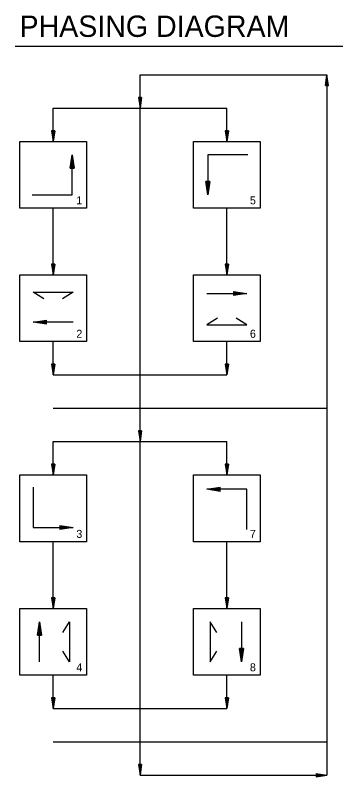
# Model space of a CAD drawing. Extents: x 1 to 35.4, y 0.4 to 10.6.
# Drawn here: x 1.154 to 3.198, y 5.838 to 10.595 of the extents above; entities that cross this region are included whole.
import ezdxf

# ---------------------------------------------------------------- set-up
doc = ezdxf.new("R2010")
doc.units = 0
for name, color, linetype in [('R_Draft', 7, 'Continuous'), ('T_Drafting', 7, 'Continuous'), ('T_Notes', 7, 'Continuous')]:
    doc.layers.add(name, color=color, linetype=linetype)

msp = doc.modelspace()

# ---------------------------------------------------------------- linework, layer by layer
at = {"layer": 'R_Draft'}
for p, q in [((3.0897, 10.1566), (3.0997, 10.2232)), ((3.0913, 10.1566), (3.0997, 10.2121)), ((3.093, 10.1566), (3.0997, 10.2006)), ((3.0947, 10.1566), (3.0997, 10.1895)), ((3.1097, 10.1566), (3.0997, 10.2232)), ((3.108, 10.1566), (3.0997, 10.2121)), ((3.1063, 10.1566), (3.0997, 10.2006)), ((3.1046, 10.1566), (3.0997, 10.1895)), ((3.0897, 10.1566), (3.1097, 10.1566)), ((3.0964, 10.1566), (3.0997, 10.1782)), ((3.0981, 10.1566), (3.0997, 10.1671)), ((3.1029, 10.1566), (3.0997, 10.1782)), ((3.1012, 10.1566), (3.0997, 10.1671)), ((1.923, 10.0816), (1.933, 10.0149)), ((1.943, 10.0816), (1.923, 10.0816)), ((1.9247, 10.0816), (1.933, 10.026)), ((1.9264, 10.0816), (1.933, 10.0375)), ((1.928, 10.0816), (1.933, 10.0486)), ((1.9297, 10.0816), (1.933, 10.0599)), ((1.9314, 10.0816), (1.933, 10.071)), ((1.943, 10.0816), (1.933, 10.0149)), ((1.9362, 10.0816), (1.933, 10.0599)), ((1.9396, 10.0816), (1.933, 10.0375)), ((1.9413, 10.0816), (1.933, 10.026)), ((1.938, 10.0816), (1.933, 10.0486)), ((1.9346, 10.0816), (1.933, 10.071)), ((1.3813, 9.8732), (1.3913, 9.8066)), ((1.4013, 9.8732), (1.3813, 9.8732)), ((1.383, 9.8732), (1.3913, 9.8177)), ((1.3847, 9.8732), (1.3913, 9.8292)), ((1.3864, 9.8732), (1.3913, 9.8403)), ((1.3881, 9.8732), (1.3913, 9.8516)), ((1.3898, 9.8732), (1.3913, 9.8627)), ((1.4013, 9.8732), (1.3913, 9.8066)), ((1.3946, 9.8732), (1.3913, 9.8516)), ((1.398, 9.8732), (1.3913, 9.8292)), ((1.3997, 9.8732), (1.3913, 9.8177)), ((1.3963, 9.8732), (1.3913, 9.8403)), ((1.3929, 9.8732), (1.3913, 9.8627)), ((2.4647, 9.8732), (2.4747, 9.8066)), ((2.4847, 9.8732), (2.4647, 9.8732)), ((2.4663, 9.8732), (2.4747, 9.8177)), ((2.468, 9.8732), (2.4747, 9.8292)), ((2.4697, 9.8732), (2.4747, 9.8403)), ((2.4714, 9.8732), (2.4747, 9.8516)), ((2.4731, 9.8732), (2.4747, 9.8627)), ((2.4847, 9.8732), (2.4747, 9.8066)), ((2.4779, 9.8732), (2.4747, 9.8516)), ((2.4813, 9.8732), (2.4747, 9.8292)), ((2.483, 9.8732), (2.4747, 9.8177)), ((2.4796, 9.8732), (2.4747, 9.8403)), ((2.4762, 9.8732), (2.4747, 9.8627)), ((1.3813, 9.0399), (1.3913, 8.9732)), ((1.4013, 9.0399), (1.3813, 9.0399)), ((1.383, 9.0399), (1.3913, 8.9844)), ((1.3847, 9.0399), (1.3913, 8.9958)), ((1.3864, 9.0399), (1.3913, 9.0069)), ((1.3881, 9.0399), (1.3913, 9.0182)), ((1.3898, 9.0399), (1.3913, 9.0294)), ((1.4013, 9.0399), (1.3913, 8.9732)), ((1.3946, 9.0399), (1.3913, 9.0182)), ((1.398, 9.0399), (1.3913, 8.9958)), ((1.3997, 9.0399), (1.3913, 8.9844)), ((1.3963, 9.0399), (1.3913, 9.0069)), ((1.3929, 9.0399), (1.3913, 9.0294)), ((2.4647, 9.0399), (2.4747, 8.9732)), ((2.4847, 9.0399), (2.4647, 9.0399)), ((2.4663, 9.0399), (2.4747, 8.9844)), ((2.468, 9.0399), (2.4747, 8.9958)), ((2.4697, 9.0399), (2.4747, 9.0069)), ((2.4714, 9.0399), (2.4747, 9.0182)), ((2.4731, 9.0399), (2.4747, 9.0294)), ((2.4847, 9.0399), (2.4747, 8.9732)), ((2.4779, 9.0399), (2.4747, 9.0182)), ((2.4813, 9.0399), (2.4747, 8.9958)), ((2.483, 9.0399), (2.4747, 8.9844)), ((2.4796, 9.0399), (2.4747, 9.0069)), ((2.4762, 9.0399), (2.4747, 9.0294)), ((1.3813, 8.4149), (1.3913, 8.3482)), ((1.4013, 8.4149), (1.3813, 8.4149)), ((1.383, 8.4149), (1.3913, 8.3594)), ((1.3847, 8.4149), (1.3913, 8.3708)), ((1.3864, 8.4149), (1.3913, 8.3819)), ((1.3881, 8.4149), (1.3913, 8.3932)), ((1.3898, 8.4149), (1.3913, 8.4044)), ((1.4013, 8.4149), (1.3913, 8.3482)), ((1.3946, 8.4149), (1.3913, 8.3932)), ((1.398, 8.4149), (1.3913, 8.3708)), ((1.3997, 8.4149), (1.3913, 8.3594)), ((1.3963, 8.4149), (1.3913, 8.3819)), ((1.3929, 8.4149), (1.3913, 8.4044)), ((2.4647, 8.4149), (2.4747, 8.3482)), ((2.4847, 8.4149), (2.4647, 8.4149)), ((2.4663, 8.4149), (2.4747, 8.3594)), ((2.468, 8.4149), (2.4747, 8.3708)), ((2.4697, 8.4149), (2.4747, 8.3819)), ((2.4714, 8.4149), (2.4747, 8.3932)), ((2.4731, 8.4149), (2.4747, 8.4044)), ((2.4847, 8.4149), (2.4747, 8.3482)), ((2.4779, 8.4149), (2.4747, 8.3932)), ((2.4813, 8.4149), (2.4747, 8.3708)), ((2.483, 8.4149), (2.4747, 8.3594)), ((2.4796, 8.4149), (2.4747, 8.3819)), ((2.4762, 8.4149), (2.4747, 8.4044)), ((1.923, 7.9982), (1.933, 7.9316)), ((1.943, 7.9982), (1.923, 7.9982)), ((1.9247, 7.9982), (1.933, 7.9427)), ((1.9264, 7.9982), (1.933, 7.9542)), ((1.928, 7.9982), (1.933, 7.9653)), ((1.9297, 7.9982), (1.933, 7.9766)), ((1.9314, 7.9982), (1.933, 7.9877)), ((1.943, 7.9982), (1.933, 7.9316)), ((1.9362, 7.9982), (1.933, 7.9766)), ((1.9396, 7.9982), (1.933, 7.9542)), ((1.9413, 7.9982), (1.933, 7.9427)), ((1.938, 7.9982), (1.933, 7.9653)), ((1.9346, 7.9982), (1.933, 7.9877)), ((1.3813, 7.7899), (1.3913, 7.7232)), ((1.4013, 7.7899), (1.3813, 7.7899)), ((1.383, 7.7899), (1.3913, 7.7344)), ((1.3847, 7.7899), (1.3913, 7.7458)), ((1.3864, 7.7899), (1.3913, 7.7569)), ((1.3881, 7.7899), (1.3913, 7.7682)), ((1.3898, 7.7899), (1.3913, 7.7794)), ((1.4013, 7.7899), (1.3913, 7.7232)), ((1.3946, 7.7899), (1.3913, 7.7682)), ((1.398, 7.7899), (1.3913, 7.7458)), ((1.3997, 7.7899), (1.3913, 7.7344)), ((1.3963, 7.7899), (1.3913, 7.7569)), ((1.3929, 7.7899), (1.3913, 7.7794)), ((2.4647, 7.7899), (2.4747, 7.7232)), ((2.4847, 7.7899), (2.4647, 7.7899)), ((2.4663, 7.7899), (2.4747, 7.7344)), ((2.468, 7.7899), (2.4747, 7.7458)), ((2.4697, 7.7899), (2.4747, 7.7569)), ((2.4714, 7.7899), (2.4747, 7.7682)), ((2.4731, 7.7899), (2.4747, 7.7794)), ((2.4847, 7.7899), (2.4747, 7.7232)), ((2.4779, 7.7899), (2.4747, 7.7682)), ((2.4813, 7.7899), (2.4747, 7.7458)), ((2.483, 7.7899), (2.4747, 7.7344)), ((2.4796, 7.7899), (2.4747, 7.7569)), ((2.4762, 7.7899), (2.4747, 7.7794)), ((1.3813, 6.9566), (1.3913, 6.8899)), ((1.4013, 6.9566), (1.3813, 6.9566)), ((1.383, 6.9566), (1.3913, 6.901)), ((1.3847, 6.9566), (1.3913, 6.9125)), ((1.3864, 6.9566), (1.3913, 6.9236)), ((1.3881, 6.9566), (1.3913, 6.9349)), ((1.3898, 6.9566), (1.3913, 6.946)), ((1.4013, 6.9566), (1.3913, 6.8899)), ((1.3946, 6.9566), (1.3913, 6.9349)), ((1.398, 6.9566), (1.3913, 6.9125)), ((1.3997, 6.9566), (1.3913, 6.901)), ((1.3963, 6.9566), (1.3913, 6.9236)), ((1.3929, 6.9566), (1.3913, 6.946)), ((2.4647, 6.9566), (2.4747, 6.8899)), ((2.4847, 6.9566), (2.4647, 6.9566)), ((2.4663, 6.9566), (2.4747, 6.901)), ((2.468, 6.9566), (2.4747, 6.9125)), ((2.4697, 6.9566), (2.4747, 6.9236)), ((2.4714, 6.9566), (2.4747, 6.9349)), ((2.4731, 6.9566), (2.4747, 6.946)), ((2.4847, 6.9566), (2.4747, 6.8899)), ((2.4779, 6.9566), (2.4747, 6.9349)), ((2.4813, 6.9566), (2.4747, 6.9125)), ((2.483, 6.9566), (2.4747, 6.901)), ((2.4796, 6.9566), (2.4747, 6.9236)), ((2.4762, 6.9566), (2.4747, 6.946)), ((1.3813, 6.3316), (1.3913, 6.2649)), ((1.4013, 6.3316), (1.3813, 6.3316)), ((1.383, 6.3316), (1.3913, 6.276)), ((1.3847, 6.3316), (1.3913, 6.2875)), ((1.3864, 6.3316), (1.3913, 6.2986)), ((1.3881, 6.3316), (1.3913, 6.3099)), ((1.3898, 6.3316), (1.3913, 6.321)), ((1.4013, 6.3316), (1.3913, 6.2649)), ((1.3946, 6.3316), (1.3913, 6.3099)), ((1.398, 6.3316), (1.3913, 6.2875)), ((1.3997, 6.3316), (1.3913, 6.276)), ((1.3963, 6.3316), (1.3913, 6.2986)), ((1.3929, 6.3316), (1.3913, 6.321)), ((2.4647, 6.3316), (2.4747, 6.2649)), ((2.4847, 6.3316), (2.4647, 6.3316)), ((2.4663, 6.3316), (2.4747, 6.276)), ((2.468, 6.3316), (2.4747, 6.2875)), ((2.4697, 6.3316), (2.4747, 6.2986)), ((2.4714, 6.3316), (2.4747, 6.3099)), ((2.4731, 6.3316), (2.4747, 6.321)), ((2.4847, 6.3316), (2.4747, 6.2649)), ((2.4779, 6.3316), (2.4747, 6.3099)), ((2.4813, 6.3316), (2.4747, 6.2875)), ((2.483, 6.3316), (2.4747, 6.276)), ((2.4796, 6.3316), (2.4747, 6.2986)), ((2.4762, 6.3316), (2.4747, 6.321)), ((1.923, 5.9149), (1.933, 5.8482)), ((1.943, 5.9149), (1.923, 5.9149)), ((1.9247, 5.9149), (1.933, 5.8594)), ((1.9264, 5.9149), (1.933, 5.8708)), ((1.928, 5.9149), (1.933, 5.8819)), ((1.9297, 5.9149), (1.933, 5.8932)), ((1.9314, 5.9149), (1.933, 5.9044)), ((1.943, 5.9149), (1.933, 5.8482)), ((1.9362, 5.9149), (1.933, 5.8932)), ((1.9396, 5.9149), (1.933, 5.8708)), ((1.9413, 5.9149), (1.933, 5.8594)), ((1.938, 5.9149), (1.933, 5.8819)), ((1.9346, 5.9149), (1.933, 5.9044)), ((3.033, 5.8582), (3.0997, 5.8482)), ((3.033, 5.8582), (3.033, 5.8382)), ((3.033, 5.8566), (3.0885, 5.8482)), ((3.033, 5.8549), (3.0771, 5.8482)), ((3.033, 5.8532), (3.066, 5.8482)), ((3.033, 5.8515), (3.0547, 5.8482)), ((3.033, 5.8498), (3.0435, 5.8482)), ((3.033, 5.8382), (3.0997, 5.8482)), ((3.033, 5.845), (3.0547, 5.8482)), ((3.033, 5.8416), (3.0771, 5.8482)), ((3.033, 5.8399), (3.0885, 5.8482)), ((3.033, 5.8433), (3.066, 5.8482)), ((3.033, 5.8467), (3.0435, 5.8482))]:
    msp.add_line(p, q, dxfattribs=at)
at = {"layer": 'T_Drafting'}
for p, q in [((1.933, 5.8482), (1.933, 10.2232)), ((1.933, 10.2232), (3.0997, 10.2232)), ((3.0997, 10.2232), (3.0997, 5.8482)), ((1.3913, 9.8066), (1.3913, 10.0149)), ((1.3913, 10.0149), (2.4747, 10.0149)), ((2.4747, 9.8066), (2.4747, 10.0149)), ((1.4976, 9.6399), (1.5101, 9.7232)), ((1.5101, 9.7093), (1.4997, 9.6399)), ((1.5101, 9.4732), (1.5101, 9.7232)), ((1.5101, 9.7232), (1.5226, 9.6399)), ((1.5205, 9.6399), (1.5101, 9.7093)), ((2.6059, 9.7232), (2.3559, 9.7232)), ((2.3559, 9.7232), (2.3559, 9.4732)), ((1.5018, 9.6399), (1.5101, 9.695)), ((1.5101, 9.6811), (1.5039, 9.6399)), ((1.5061, 9.6399), (1.5101, 9.667)), ((1.5101, 9.695), (1.5184, 9.6399)), ((1.5163, 9.6399), (1.5101, 9.6811)), ((1.5101, 9.667), (1.5142, 9.6399)), ((1.4976, 9.6399), (1.5226, 9.6399)), ((1.5101, 9.6531), (1.5081, 9.6399)), ((1.5121, 9.6399), (1.5101, 9.6531)), ((2.3559, 9.4732), (2.3434, 9.5566)), ((2.3684, 9.5566), (2.3434, 9.5566)), ((2.3455, 9.5566), (2.3559, 9.4871)), ((2.3559, 9.5015), (2.3476, 9.5566)), ((2.3497, 9.5566), (2.3559, 9.5153)), ((2.3559, 9.5295), (2.3518, 9.5566)), ((2.354, 9.5566), (2.3559, 9.5434)), ((2.3559, 9.5434), (2.3579, 9.5566)), ((2.36, 9.5566), (2.3559, 9.5295)), ((2.3559, 9.5153), (2.3621, 9.5566)), ((2.3642, 9.5566), (2.3559, 9.5015)), ((2.3559, 9.4871), (2.3663, 9.5566)), ((2.3684, 9.5566), (2.3559, 9.4732)), ((1.2601, 9.4732), (1.5101, 9.4732)), ((1.3913, 8.9732), (1.3913, 9.3899)), ((2.4747, 8.9732), (2.4747, 9.3899)), ((2.3497, 8.856), (2.5997, 8.856)), ((2.5163, 8.8685), (2.5997, 8.856)), ((2.5163, 8.8685), (2.5163, 8.8435)), ((2.5858, 8.856), (2.5163, 8.8664)), ((2.5163, 8.8643), (2.5714, 8.856)), ((2.5576, 8.856), (2.5163, 8.8622)), ((2.5163, 8.86), (2.5434, 8.856)), ((2.5295, 8.856), (2.5163, 8.858)), ((2.5997, 8.856), (2.5163, 8.8435)), ((2.5163, 8.8456), (2.5858, 8.856)), ((2.5714, 8.856), (2.5163, 8.8477)), ((2.5163, 8.8498), (2.5576, 8.856)), ((2.5434, 8.856), (2.5163, 8.8519)), ((2.5163, 8.854), (2.5295, 8.856)), ((1.2663, 8.6779), (1.3497, 8.6904)), ((1.5163, 8.6779), (1.2663, 8.6779)), ((1.3497, 8.6654), (1.2663, 8.6779)), ((1.3497, 8.6884), (1.2803, 8.6779)), ((1.2803, 8.6779), (1.3497, 8.6675)), ((1.2946, 8.6779), (1.3497, 8.6862)), ((1.3497, 8.6696), (1.2946, 8.6779)), ((1.3497, 8.6841), (1.3085, 8.6779)), ((1.3085, 8.6779), (1.3497, 8.6717)), ((1.3226, 8.6779), (1.3497, 8.682)), ((1.3497, 8.6739), (1.3226, 8.6779)), ((1.3497, 8.6799), (1.3365, 8.6779)), ((1.3365, 8.6779), (1.3497, 8.676)), ((1.3497, 8.6654), (1.3497, 8.6904)), ((1.3913, 8.3482), (1.3913, 8.5566)), ((2.4747, 8.3482), (2.4747, 8.5566)), ((1.3913, 8.3482), (2.4747, 8.3482)), ((1.3913, 8.1399), (3.0997, 8.1399)), ((1.3913, 7.9316), (2.4747, 7.9316)), ((1.3913, 7.7232), (1.3913, 7.9316)), ((2.4747, 7.7232), (2.4747, 7.9316)), ((1.2663, 7.6461), (1.2663, 7.3961)), ((2.3497, 7.6336), (2.433, 7.6461)), ((2.5997, 7.6336), (2.3497, 7.6336)), ((2.433, 7.6211), (2.3497, 7.6336)), ((2.433, 7.6441), (2.3636, 7.6336)), ((2.3636, 7.6336), (2.433, 7.6232)), ((2.3779, 7.6336), (2.433, 7.6419)), ((2.433, 7.6253), (2.3779, 7.6336)), ((2.433, 7.6398), (2.3918, 7.6336)), ((2.3918, 7.6336), (2.433, 7.6274)), ((2.4059, 7.6336), (2.433, 7.6377)), ((2.433, 7.6296), (2.4059, 7.6336)), ((2.433, 7.6356), (2.4198, 7.6336)), ((2.4198, 7.6336), (2.433, 7.6317)), ((2.433, 7.6211), (2.433, 7.6461)), ((2.5997, 7.3836), (2.5997, 7.6336)), ((1.2663, 7.3961), (1.5163, 7.3961)), ((1.433, 7.4086), (1.5163, 7.3961)), ((1.433, 7.4086), (1.433, 7.3836)), ((1.5024, 7.3961), (1.433, 7.4066)), ((1.433, 7.4044), (1.4881, 7.3961)), ((1.4742, 7.3961), (1.433, 7.4023)), ((1.433, 7.4002), (1.4601, 7.3961)), ((1.4462, 7.3961), (1.433, 7.3981)), ((1.5163, 7.3961), (1.433, 7.3836)), ((1.433, 7.3857), (1.5024, 7.3961)), ((1.4881, 7.3961), (1.433, 7.3878)), ((1.433, 7.3899), (1.4742, 7.3961)), ((1.4601, 7.3961), (1.433, 7.3921)), ((1.433, 7.3942), (1.4462, 7.3961)), ((1.3913, 6.8899), (1.3913, 7.3066)), ((2.4747, 6.8899), (2.4747, 7.3066)), ((1.2932, 6.7227), (1.3057, 6.806)), ((1.3057, 6.556), (1.3057, 6.806)), ((1.3057, 6.806), (1.3182, 6.7227)), ((2.5662, 6.8056), (2.5662, 6.5556)), ((1.3057, 6.7921), (1.2953, 6.7227)), ((1.2974, 6.7227), (1.3057, 6.7778)), ((1.3057, 6.7639), (1.2995, 6.7227)), ((1.3161, 6.7227), (1.3057, 6.7921)), ((1.3057, 6.7778), (1.314, 6.7227)), ((1.3119, 6.7227), (1.3057, 6.7639)), ((1.2932, 6.7227), (1.3182, 6.7227)), ((1.3016, 6.7227), (1.3057, 6.7498)), ((1.3057, 6.7359), (1.3037, 6.7227)), ((1.3057, 6.7498), (1.3098, 6.7227)), ((1.3076, 6.7227), (1.3057, 6.7359)), ((2.5662, 6.5556), (2.5537, 6.6389)), ((2.5787, 6.6389), (2.5537, 6.6389)), ((2.5558, 6.6389), (2.5662, 6.5695)), ((2.5662, 6.5839), (2.5579, 6.6389)), ((2.56, 6.6389), (2.5662, 6.5977)), ((2.5662, 6.6119), (2.5621, 6.6389)), ((2.5642, 6.6389), (2.5662, 6.6258)), ((2.5662, 6.6258), (2.5681, 6.6389)), ((2.5702, 6.6389), (2.5662, 6.6119)), ((2.5662, 6.5977), (2.5724, 6.6389)), ((2.5745, 6.6389), (2.5662, 6.5839)), ((2.5662, 6.5695), (2.5766, 6.6389)), ((2.5787, 6.6389), (2.5662, 6.5556)), ((1.3913, 6.2649), (1.3913, 6.4732)), ((2.4747, 6.2649), (2.4747, 6.4732)), ((1.3913, 6.2649), (2.4747, 6.2649)), ((1.3913, 6.0566), (3.0997, 6.0566)), ((1.933, 5.8482), (3.0997, 5.8482))]:
    msp.add_line(p, q, dxfattribs=at)
for points in [[(1.183, 9.8066), (1.5997, 9.8066), (1.5997, 9.3899), (1.183, 9.3899)], [(2.2663, 9.8066), (2.683, 9.8066), (2.683, 9.3899), (2.2663, 9.3899)], [(1.183, 8.9732), (1.5997, 8.9732), (1.5997, 8.5566), (1.183, 8.5566)], [(2.2663, 8.9732), (2.683, 8.9732), (2.683, 8.5566), (2.2663, 8.5566)], [(1.183, 7.7232), (1.5997, 7.7232), (1.5997, 7.3066), (1.183, 7.3066)], [(2.2663, 7.7232), (2.683, 7.7232), (2.683, 7.3066), (2.2663, 7.3066)], [(1.183, 6.8899), (1.5997, 6.8899), (1.5997, 6.4732), (1.183, 6.4732)], [(2.2663, 6.8899), (2.683, 6.8899), (2.683, 6.4732), (2.2663, 6.4732)]]:
    msp.add_lwpolyline(points, close=True, dxfattribs=at)
for points in [[(1.333, 8.8227), (1.2663, 8.8643), (1.5163, 8.8643), (1.4497, 8.8227)], [(2.4163, 8.7029), (2.3497, 8.6613), (2.5997, 8.6613), (2.533, 8.7029)], [(1.4504, 6.7394), (1.4921, 6.806), (1.4921, 6.556), (1.4504, 6.6227)], [(2.4131, 6.7389), (2.3715, 6.8056), (2.3715, 6.5556), (2.4131, 6.6223)]]:
    msp.add_lwpolyline(points, dxfattribs=at)
at = {"layer": 'T_Notes'}
msp.add_line((1.1542, 10.4018), (3.1983, 10.4018), dxfattribs=at)

# ---------------------------------------------------------------- texts
for s, height, p in [('PHASING DIAGRAM', 0.133333, (1.1809, 10.4596)), ('1', 0.05, (1.5356, 9.4136)), ('5', 0.05, (2.6189, 9.4136)), ('2', 0.05, (1.5356, 8.5803)), ('6', 0.05, (2.6189, 8.5803)), ('3', 0.05, (1.5356, 7.3303)), ('7', 0.05, (2.6189, 7.3303)), ('4', 0.05, (1.5356, 6.4969)), ('8', 0.05, (2.6189, 6.4969))]:
    msp.add_text(s, height=height, dxfattribs=at).set_placement(p)

doc.saveas('drawing.dxf')
